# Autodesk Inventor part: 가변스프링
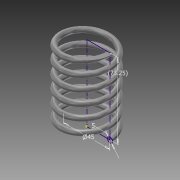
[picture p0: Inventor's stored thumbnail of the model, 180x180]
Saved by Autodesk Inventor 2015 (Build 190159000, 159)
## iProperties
Created: 2015-10
Part Number: 가변스프링
Material: Steel, Mild
Document SubType Name: Modeling
Designer: youjin07
Mass: 128.859 g
Surface Area: 133.055 cm^2
Volume: 16.4151 cm^3
Density: 7.85 g/cm^3
Appearance: Semi-Polished
Author: youjin07
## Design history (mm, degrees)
sketch "Sketch1"
  geometry: L1 (-22.5, 73.25)-(0, 73.25); L2 (0, 73.25)-(0, 0); L3 (0, 0)-(-22.5, 0); L4 (-22.5, 0)-(-22.5, 73.25); C1 r 2.5 at (-22.5, 0); 1 further point
  constraints: 8 end point, 2 coincident, 2 parallel, 1 centre point, 1 horizontal, 1 perpendicular
  dimensions: "d0" = 45 diameter of L4 L2; "d1" = 73.25 distance between parallel lines of L1 L3 (derived); "d2" = 5 diameter of C1
coil "Coil1" sketch "Sketch1" pitch "d3" = 10; turns "d5" = 6; dims "d4" = 73.25 (= d1), "d6" = 0, angle "d7" = 90 deg, angle "d8" = 90 deg, "d9" = 0, "d10" = 0
sketch "Sketch2"
  geometry: L1 (25, 0)-(20, 0) reference; 1 further point
  constraints: 1 horizontal alignment
extrude "Extrusion1" cut sketch "Sketch2" stored distance "d11" = 10; taper "d12" = 0 deg
workplane "Work Plane1"
sketch "Sketch3"
  geometry: L1 (-25, 0)-(-20, 0) reference; 1 further point
  constraints: 1 horizontal alignment
extrude "Extrusion2" cut sketch "Sketch3" stored distance "d13" = 10; taper "d14" = 0 deg
body "Solid1"
node "Project Cut Edges1"
node "Project Cut Edges2"
